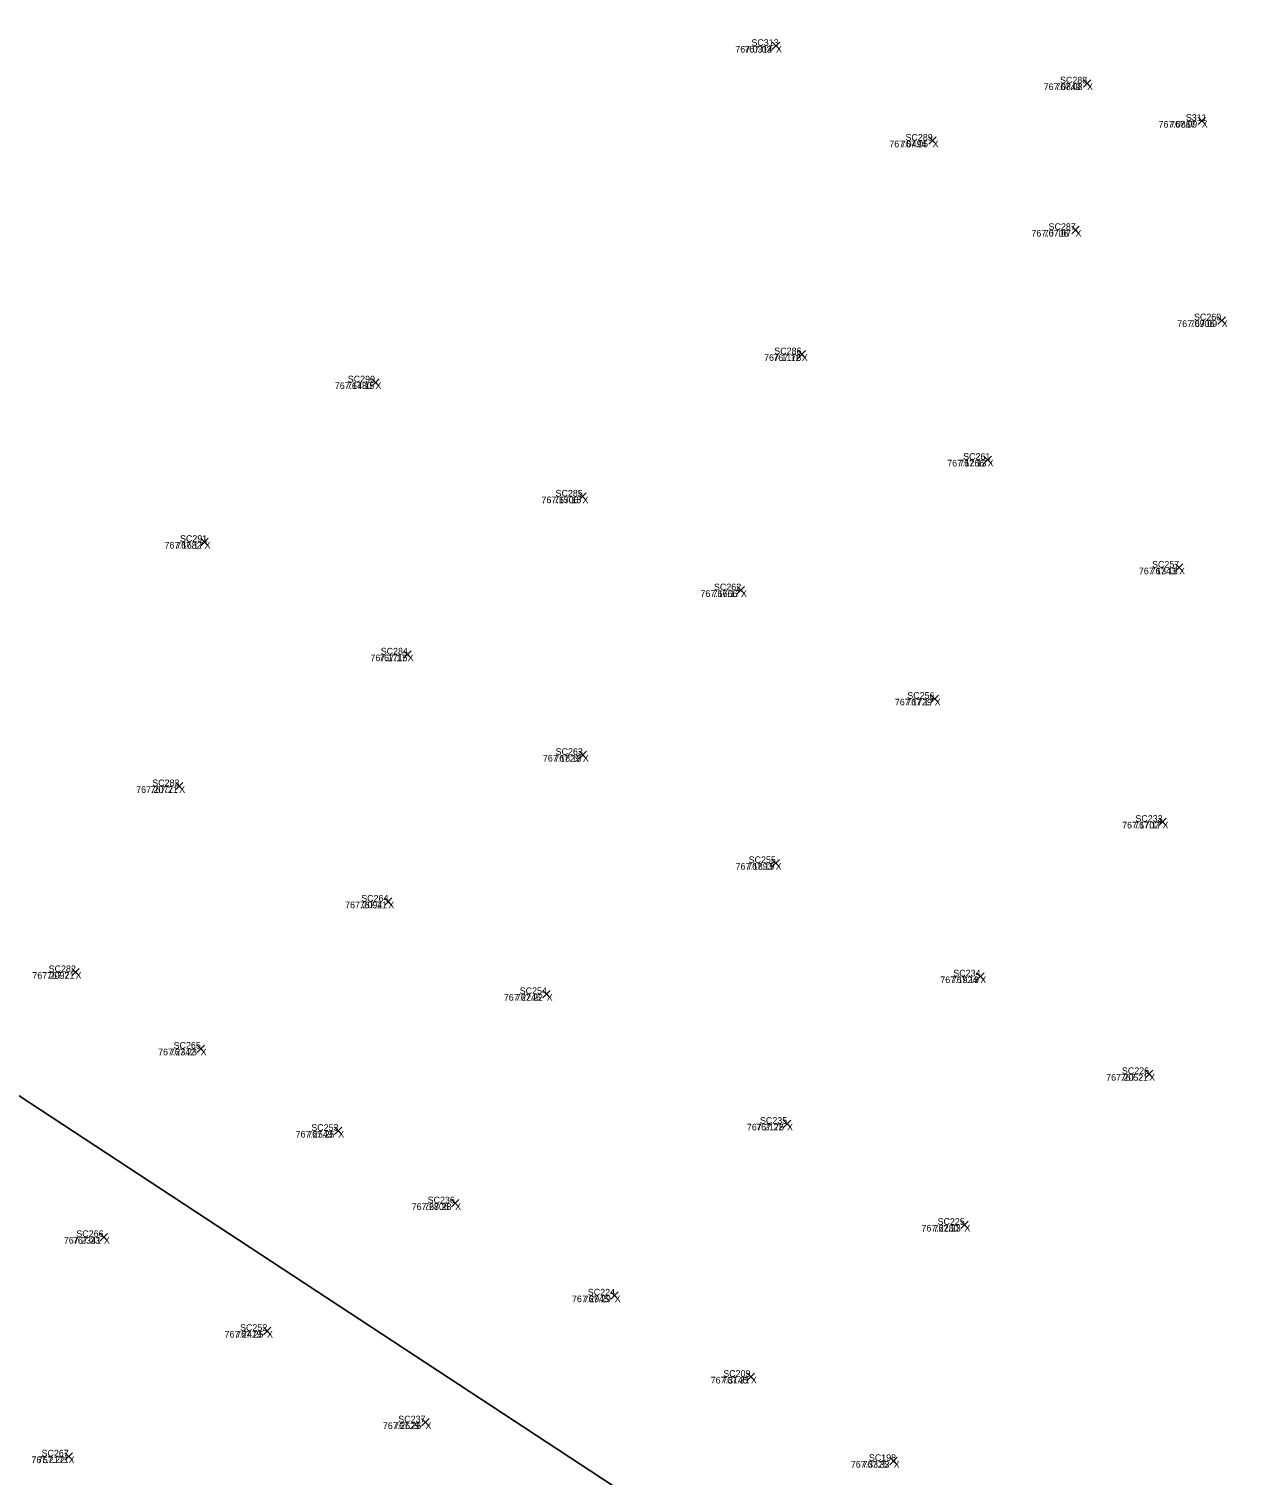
# Model space of a CAD drawing. Extents: x 1845019 to 1877956, y 680444 to 701081.
# Drawn here: x 1857662.57 to 1857673.65, y 694277.24 to 694290.28 of the extents above; entities that cross this region are included whole.
import ezdxf

# ---------------------------------------------------------------- set-up
doc = ezdxf.new("R2010")
doc.units = 0
for name, color, linetype in [('SV_X_CL_Survey_20', 7, 'Continuous'), ('SV_X_Random_Point', 7, 'Continuous'), ('SV_X_Text_Comment', 7, 'Continuous'), ('SV_X_Text_Elevation', 7, 'Continuous'), ('SV_X_Text_Name', 7, 'Continuous')]:
    doc.layers.add(name, color=color, linetype=linetype)

msp = doc.modelspace()

# ---------------------------------------------------------------- linework, layer by layer
at = {"layer": 'SV_X_CL_Survey_20'}
msp.add_line((1856038.267, 695346.314), (1858797.327, 693536.085), dxfattribs=at)
at = {"layer": 'SV_X_Random_Point'}
for p, q in [((1857669.269, 694290.094), (1857669.336, 694290.161)), ((1857669.269, 694290.161), (1857669.336, 694290.094)), ((1857669.269, 694290.094), (1857669.336, 694290.161)), ((1857669.269, 694290.161), (1857669.336, 694290.094)), ((1857672.074, 694289.755), (1857672.14, 694289.822)), ((1857672.074, 694289.822), (1857672.14, 694289.755)), ((1857672.074, 694289.755), (1857672.14, 694289.822)), ((1857672.074, 694289.822), (1857672.14, 694289.755)), ((1857673.108, 694289.418), (1857673.175, 694289.485)), ((1857673.108, 694289.485), (1857673.175, 694289.418)), ((1857673.108, 694289.418), (1857673.175, 694289.485)), ((1857673.108, 694289.485), (1857673.175, 694289.418)), ((1857670.681, 694289.24), (1857670.748, 694289.306)), ((1857670.681, 694289.306), (1857670.748, 694289.24)), ((1857670.681, 694289.24), (1857670.748, 694289.306)), ((1857670.681, 694289.306), (1857670.748, 694289.24)), ((1857671.97, 694288.434), (1857672.036, 694288.501)), ((1857671.97, 694288.501), (1857672.036, 694288.434)), ((1857671.97, 694288.434), (1857672.036, 694288.501)), ((1857671.97, 694288.501), (1857672.036, 694288.434)), ((1857673.287, 694287.62), (1857673.354, 694287.686)), ((1857673.287, 694287.686), (1857673.354, 694287.62)), ((1857673.287, 694287.62), (1857673.354, 694287.686)), ((1857673.287, 694287.686), (1857673.354, 694287.62)), ((1857669.501, 694287.313), (1857669.568, 694287.38)), ((1857669.501, 694287.38), (1857669.568, 694287.313)), ((1857669.501, 694287.313), (1857669.568, 694287.38)), ((1857669.501, 694287.38), (1857669.568, 694287.313)), ((1857665.658, 694287.06), (1857665.724, 694287.127)), ((1857665.658, 694287.127), (1857665.724, 694287.06)), ((1857665.658, 694287.06), (1857665.724, 694287.127)), ((1857665.658, 694287.127), (1857665.724, 694287.06)), ((1857671.177, 694286.362), (1857671.244, 694286.429)), ((1857671.177, 694286.429), (1857671.244, 694286.362)), ((1857671.177, 694286.362), (1857671.244, 694286.429)), ((1857671.177, 694286.429), (1857671.244, 694286.362)), ((1857667.525, 694286.032), (1857667.591, 694286.098)), ((1857667.525, 694286.098), (1857667.591, 694286.032)), ((1857667.525, 694286.032), (1857667.591, 694286.098)), ((1857667.525, 694286.098), (1857667.591, 694286.032)), ((1857664.117, 694285.622), (1857664.184, 694285.689)), ((1857664.117, 694285.689), (1857664.184, 694285.622)), ((1857664.117, 694285.622), (1857664.184, 694285.689)), ((1857664.117, 694285.689), (1857664.184, 694285.622)), ((1857672.903, 694285.391), (1857672.969, 694285.458)), ((1857672.903, 694285.458), (1857672.969, 694285.391)), ((1857672.903, 694285.391), (1857672.969, 694285.458)), ((1857672.903, 694285.458), (1857672.969, 694285.391)), ((1857668.954, 694285.187), (1857669.02, 694285.254)), ((1857668.954, 694285.254), (1857669.02, 694285.187)), ((1857668.954, 694285.187), (1857669.02, 694285.254)), ((1857668.954, 694285.254), (1857669.02, 694285.187)), ((1857665.948, 694284.608), (1857666.015, 694284.674)), ((1857665.948, 694284.674), (1857666.015, 694284.608)), ((1857665.948, 694284.608), (1857666.015, 694284.674)), ((1857665.948, 694284.674), (1857666.015, 694284.608)), ((1857670.7, 694284.209), (1857670.767, 694284.276)), ((1857670.7, 694284.276), (1857670.767, 694284.209)), ((1857670.7, 694284.209), (1857670.767, 694284.276)), ((1857670.7, 694284.276), (1857670.767, 694284.209)), ((1857667.527, 694283.702), (1857667.594, 694283.769)), ((1857667.527, 694283.769), (1857667.594, 694283.702)), ((1857667.527, 694283.702), (1857667.594, 694283.769)), ((1857667.527, 694283.769), (1857667.594, 694283.702)), ((1857663.889, 694283.42), (1857663.955, 694283.487)), ((1857663.889, 694283.487), (1857663.955, 694283.42)), ((1857663.889, 694283.42), (1857663.955, 694283.487)), ((1857663.889, 694283.487), (1857663.955, 694283.42)), ((1857672.754, 694283.1), (1857672.821, 694283.167)), ((1857672.754, 694283.167), (1857672.821, 694283.1)), ((1857672.754, 694283.1), (1857672.821, 694283.167)), ((1857672.754, 694283.167), (1857672.821, 694283.1)), ((1857669.266, 694282.727), (1857669.333, 694282.794)), ((1857669.266, 694282.794), (1857669.333, 694282.727)), ((1857669.266, 694282.727), (1857669.333, 694282.794)), ((1857669.266, 694282.794), (1857669.333, 694282.727)), ((1857665.774, 694282.38), (1857665.84, 694282.447)), ((1857665.774, 694282.447), (1857665.84, 694282.38)), ((1857665.774, 694282.38), (1857665.84, 694282.447)), ((1857665.774, 694282.447), (1857665.84, 694282.38)), ((1857662.954, 694281.744), (1857663.021, 694281.811)), ((1857662.954, 694281.811), (1857663.021, 694281.744)), ((1857662.954, 694281.744), (1857663.021, 694281.811)), ((1857662.954, 694281.811), (1857663.021, 694281.744)), ((1857671.111, 694281.706), (1857671.178, 694281.773)), ((1857671.111, 694281.773), (1857671.178, 694281.706)), ((1857671.111, 694281.706), (1857671.178, 694281.773)), ((1857671.111, 694281.773), (1857671.178, 694281.706)), ((1857667.202, 694281.547), (1857667.268, 694281.613)), ((1857667.202, 694281.613), (1857667.268, 694281.547)), ((1857667.202, 694281.547), (1857667.268, 694281.613)), ((1857667.202, 694281.613), (1857667.268, 694281.547)), ((1857664.083, 694281.054), (1857664.149, 694281.121)), ((1857664.083, 694281.121), (1857664.149, 694281.054)), ((1857664.083, 694281.054), (1857664.149, 694281.121)), ((1857664.083, 694281.121), (1857664.149, 694281.054)), ((1857672.634, 694280.826), (1857672.701, 694280.893)), ((1857672.634, 694280.893), (1857672.701, 694280.826)), ((1857672.634, 694280.826), (1857672.701, 694280.893)), ((1857672.634, 694280.893), (1857672.701, 694280.826)), ((1857669.369, 694280.378), (1857669.436, 694280.444)), ((1857669.369, 694280.444), (1857669.436, 694280.378)), ((1857669.369, 694280.378), (1857669.436, 694280.444)), ((1857669.369, 694280.444), (1857669.436, 694280.378)), ((1857665.323, 694280.314), (1857665.389, 694280.38)), ((1857665.323, 694280.38), (1857665.389, 694280.314)), ((1857665.323, 694280.314), (1857665.389, 694280.38)), ((1857665.323, 694280.38), (1857665.389, 694280.314)), ((1857666.377, 694279.661), (1857666.444, 694279.728)), ((1857666.377, 694279.728), (1857666.444, 694279.661)), ((1857666.377, 694279.661), (1857666.444, 694279.728)), ((1857666.377, 694279.728), (1857666.444, 694279.661)), ((1857670.968, 694279.466), (1857671.034, 694279.533)), ((1857670.968, 694279.533), (1857671.034, 694279.466)), ((1857670.968, 694279.466), (1857671.034, 694279.533)), ((1857670.968, 694279.533), (1857671.034, 694279.466)), ((1857663.209, 694279.357), (1857663.276, 694279.423)), ((1857663.209, 694279.423), (1857663.276, 694279.357)), ((1857663.209, 694279.357), (1857663.276, 694279.423)), ((1857663.209, 694279.423), (1857663.276, 694279.357)), ((1857667.815, 694278.829), (1857667.881, 694278.896)), ((1857667.815, 694278.896), (1857667.881, 694278.829)), ((1857667.815, 694278.829), (1857667.881, 694278.896)), ((1857667.815, 694278.896), (1857667.881, 694278.829)), ((1857664.681, 694278.51), (1857664.747, 694278.577)), ((1857664.681, 694278.577), (1857664.747, 694278.51)), ((1857664.681, 694278.51), (1857664.747, 694278.577)), ((1857664.681, 694278.577), (1857664.747, 694278.51)), ((1857669.043, 694278.097), (1857669.11, 694278.163)), ((1857669.043, 694278.163), (1857669.11, 694278.097)), ((1857669.043, 694278.097), (1857669.11, 694278.163)), ((1857669.043, 694278.163), (1857669.11, 694278.097)), ((1857666.108, 694277.686), (1857666.175, 694277.753)), ((1857666.108, 694277.753), (1857666.175, 694277.686)), ((1857666.108, 694277.686), (1857666.175, 694277.753)), ((1857666.108, 694277.753), (1857666.175, 694277.686)), ((1857662.892, 694277.379), (1857662.959, 694277.446)), ((1857662.892, 694277.446), (1857662.959, 694277.379)), ((1857662.892, 694277.379), (1857662.959, 694277.446)), ((1857662.892, 694277.446), (1857662.959, 694277.379)), ((1857670.329, 694277.338), (1857670.396, 694277.405)), ((1857670.329, 694277.405), (1857670.396, 694277.338)), ((1857670.329, 694277.338), (1857670.396, 694277.405)), ((1857670.329, 694277.405), (1857670.396, 694277.338))]:
    msp.add_line(p, q, dxfattribs=at)

# ---------------------------------------------------------------- texts
at = {"layer": 'SV_X_Text_Comment'}
for p in [(1857669.302, 694290.067), (1857672.107, 694289.729), (1857673.141, 694289.391), (1857670.714, 694289.213), (1857672.003, 694288.408), (1857673.321, 694287.593), (1857669.535, 694287.287), (1857665.691, 694287.034), (1857671.21, 694286.336), (1857667.558, 694286.005), (1857664.151, 694285.596), (1857672.936, 694285.364), (1857668.987, 694285.16), (1857665.982, 694284.581), (1857670.733, 694284.182), (1857667.561, 694283.676), (1857663.922, 694283.394), (1857672.787, 694283.073), (1857669.299, 694282.701), (1857665.807, 694282.354), (1857662.988, 694281.718), (1857671.144, 694281.679), (1857667.235, 694281.52), (1857664.116, 694281.028), (1857672.667, 694280.799), (1857669.402, 694280.351), (1857665.356, 694280.287), (1857666.41, 694279.634), (1857671.001, 694279.44), (1857663.243, 694279.33), (1857667.848, 694278.803), (1857664.714, 694278.484), (1857669.076, 694278.07), (1857666.142, 694277.659), (1857662.925, 694277.352), (1857670.363, 694277.311)]:
    msp.add_text('X', height=0.06, dxfattribs=at).set_placement(p)
at = {"layer": 'SV_X_Text_Elevation'}
for s, p in [('767.0314', (1857668.936, 694290.067)), ('767.03', (1857669.017, 694290.067)), ('767.0849', (1857671.716, 694289.729)), ('767.08', (1857671.821, 694289.729)), ('767.0867', (1857672.751, 694289.391)), ('767.09', (1857672.855, 694289.391)), ('767.0494', (1857670.324, 694289.213)), ('767.05', (1857670.428, 694289.213)), ('767.0706', (1857671.605, 694288.408)), ('767.07', (1857671.717, 694288.408)), ('767.0906', (1857672.92, 694287.593)), ('767.09', (1857673.034, 694287.593)), ('767.1176', (1857669.195, 694287.287)), ('767.12', (1857669.278, 694287.287)), ('767.1480', (1857665.325, 694287.034)), ('767.15', (1857665.435, 694287.034)), ('767.1266', (1857670.846, 694286.336)), ('767.13', (1857670.954, 694286.336)), ('767.1506', (1857667.188, 694286.005)), ('767.15', (1857667.302, 694286.005)), ('767.1682', (1857663.79, 694285.596)), ('767.17', (1857663.894, 694285.596)), ('767.1343', (1857672.574, 694285.364)), ('767.13', (1857672.68, 694285.364)), ('767.1666', (1857668.621, 694285.16)), ('767.17', (1857668.73, 694285.16)), ('767.1715', (1857665.646, 694284.581)), ('767.17', (1857665.725, 694284.581)), ('767.1729', (1857670.374, 694284.182)), ('767.17', (1857670.477, 694284.182)), ('767.1829', (1857667.201, 694283.676)), ('767.18', (1857667.304, 694283.676)), ('767.2077', (1857663.534, 694283.394)), ('767.21', (1857663.665, 694283.394)), ('767.1702', (1857672.423, 694283.073)), ('767.17', (1857672.531, 694283.073)), ('767.1893', (1857668.938, 694282.701)), ('767.19', (1857669.042, 694282.701)), ('767.2094', (1857665.418, 694282.354)), ('767.21', (1857665.55, 694282.354)), ('767.2097', (1857662.598, 694281.718)), ('767.21', (1857662.731, 694281.718)), ('767.1924', (1857670.784, 694281.679)), ('767.19', (1857670.887, 694281.679)), ('767.2246', (1857666.849, 694281.52)), ('767.22', (1857666.956, 694281.52)), ('767.2342', (1857663.732, 694281.028)), ('767.23', (1857663.837, 694281.028)), ('767.2052', (1857672.279, 694280.799)), ('767.21', (1857672.411, 694280.799)), ('767.2176', (1857669.04, 694280.351)), ('767.22', (1857669.124, 694280.351)), ('767.2549', (1857664.972, 694280.287)), ('767.25', (1857665.077, 694280.287)), ('767.2806', (1857666.018, 694279.634)), ('767.28', (1857666.131, 694279.634)), ('767.2280', (1857670.614, 694279.44)), ('767.23', (1857670.722, 694279.44)), ('767.2341', (1857662.882, 694279.33)), ('767.23', (1857662.964, 694279.33)), ('767.2945', (1857667.463, 694278.803)), ('767.29', (1857667.568, 694278.803)), ('767.2479', (1857664.331, 694278.484)), ('767.25', (1857664.435, 694278.484)), ('767.3145', (1857668.714, 694278.07)), ('767.31', (1857668.818, 694278.07)), ('767.2629', (1857665.758, 694277.659)), ('767.26', (1857665.859, 694277.659)), ('767.2171', (1857662.59, 694277.352)), ('767.22', (1857662.647, 694277.352)), ('767.3325', (1857669.977, 694277.311)), ('767.33', (1857670.081, 694277.311))]:
    msp.add_text(s, height=0.06, dxfattribs=at).set_placement(p)
at = {"layer": 'SV_X_Text_Name'}
for s, p in [('SC313', (1857669.081, 694290.127)), ('SC313', (1857669.081, 694290.127)), ('SC288', (1857671.863, 694289.789)), ('SC288', (1857671.863, 694289.789)), ('S311', (1857672.997, 694289.451)), ('S311', (1857672.998, 694289.451)), ('SC289', (1857670.47, 694289.273)), ('SC289', (1857670.47, 694289.273)), ('SC287', (1857671.76, 694288.468)), ('SC287', (1857671.76, 694288.468)), ('SC260', (1857673.071, 694287.653)), ('SC260', (1857673.071, 694287.653)), ('SC286', (1857669.287, 694287.347)), ('SC286', (1857669.287, 694287.347)), ('SC290', (1857665.442, 694287.094)), ('SC290', (1857665.442, 694287.094)), ('SC261', (1857670.989, 694286.396)), ('SC261', (1857670.99, 694286.396)), ('SC285', (1857667.315, 694286.065)), ('SC285', (1857667.315, 694286.065)), ('SC291', (1857663.929, 694285.656)), ('SC291', (1857663.93, 694285.656)), ('SC257', (1857672.693, 694285.424)), ('SC257', (1857672.693, 694285.424)), ('SC262', (1857668.743, 694285.22)), ('SC262', (1857668.743, 694285.22)), ('SC284', (1857665.739, 694284.641)), ('SC284', (1857665.739, 694284.641)), ('SC256', (1857670.486, 694284.242)), ('SC256', (1857670.486, 694284.242)), ('SC263', (1857667.316, 694283.736)), ('SC263', (1857667.316, 694283.736)), ('SC283', (1857663.679, 694283.454)), ('SC283', (1857663.679, 694283.454)), ('SC233', (1857672.543, 694283.133)), ('SC233', (1857672.543, 694283.133)), ('SC255', (1857669.056, 694282.761)), ('SC255', (1857669.056, 694282.761)), ('SC264', (1857665.563, 694282.414)), ('SC264', (1857665.563, 694282.414)), ('SC282', (1857662.745, 694281.778)), ('SC282', (1857662.745, 694281.778)), ('SC234', (1857670.901, 694281.739)), ('SC234', (1857670.901, 694281.739)), ('SC254', (1857666.992, 694281.58)), ('SC254', (1857666.992, 694281.58)), ('SC265', (1857663.872, 694281.088)), ('SC265', (1857663.872, 694281.088)), ('SC226', (1857672.421, 694280.859)), ('SC226', (1857672.421, 694280.859)), ('SC253', (1857665.113, 694280.347)), ('SC253', (1857665.113, 694280.347)), ('SC235', (1857669.158, 694280.411)), ('SC235', (1857669.158, 694280.411)), ('SC236', (1857666.162, 694279.694)), ('SC236', (1857666.162, 694279.694)), ('SC225', (1857670.759, 694279.5)), ('SC225', (1857670.759, 694279.5)), ('SC266', (1857662.995, 694279.39)), ('SC266', (1857662.995, 694279.39)), ('SC224', (1857667.606, 694278.863)), ('SC224', (1857667.606, 694278.863)), ('SC252', (1857664.471, 694278.544)), ('SC252', (1857664.471, 694278.544)), ('SC209', (1857668.827, 694278.13)), ('SC209', (1857668.827, 694278.13)), ('SC237', (1857665.897, 694277.719)), ('SC237', (1857665.897, 694277.719)), ('SC267', (1857662.681, 694277.412)), ('SC267', (1857662.681, 694277.412)), ('SC198', (1857670.14, 694277.371)), ('SC198', (1857670.14, 694277.371))]:
    msp.add_text(s, height=0.06, dxfattribs=at).set_placement(p)

doc.saveas('drawing.dxf')
